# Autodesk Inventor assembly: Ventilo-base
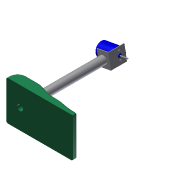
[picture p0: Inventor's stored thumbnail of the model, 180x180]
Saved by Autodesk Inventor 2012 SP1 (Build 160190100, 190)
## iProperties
Created: 2012-06
Part Number: Ventilo-base
Document SubType Name: Assembly
Designer: Bruno
Author: Bruno
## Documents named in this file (8)
- D:\Cours\1-Cours-2012-13\My Box Files\1-ITEC\9-Cinématique-V=W.R-Ventilo\ventilo-2\Ventilo-base.iam
- D:\Cours\1-Cours-2012-13\My Box Files\1-ITEC\9-Cinématique-V=W.R-Ventilo\ventilo-2\Axe.ipt
- D:\Cours\1-Cours-2012-13\My Box Files\1-ITEC\9-Cinématique-V=W.R-Ventilo\ventilo-2\Axe-moteur.ipt
- D:\Cours\1-Cours-2012-13\My Box Files\1-ITEC\9-Cinématique-V=W.R-Ventilo\ventilo-2\corps-moteur.ipt
- D:\Cours\1-Cours-2012-13\My Box Files\1-ITEC\9-Cinématique-V=W.R-Ventilo\ventilo-2\equerre.ipt
- C:\Users\Bruno\Documents\Inventor\Content Center Files\R2012\fr-FR\ANSI B18.6.7M(02)\ANSI B18.6.7M - M4x0,7 x 10(6).ipt
- C:\Users\Bruno\Documents\Inventor\Content Center Files\R2012\fr-FR\JIS B 1111  H (2)\JIS B 1111 - A M2 x 8 - H(1).ipt
- D:\Cours\1-Cours-2012-13\My Box Files\1-ITEC\9-Cinématique-V=W.R-Ventilo\ventilo-2\embase-2.ipt
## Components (8 placed, 7 different names)
1. embase-2:1 — Logement:23
2. Axe:1 — Logement:12, Logement:23
3. Axe-moteur:1 — Placage:4, Affleurement:1
4. corps-moteur:1 — Placage:4, Affleurement:1, Affleurement:2, Placage:16
5. equerre:1 — Affleurement:2, Logement:12, Logement:13, Placage:16, Logement:14, Logement:15
6. Vis à tête carrée - Type III - Métrique M4x0,7 x 10:1 — Logement:13
7. JIS B 1111 H - Métrique A M2 x 8 - H:1 — Logement:14
8. JIS B 1111 H - Métrique A M2 x 8 - H:2 — Logement:15
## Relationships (9: Insert 5, Mate 2, Flush 2)
- Placage:4 [Mate]: Axe-moteur:1 ↔ corps-moteur:1
- Affleurement:1 [Flush]: Axe-moteur:1 ↔ corps-moteur:1
- Affleurement:2 [Flush]: corps-moteur:1 ↔ equerre:1
- Logement:12 [Insert]: Axe:1 ↔ equerre:1
- Logement:13 [Insert]: equerre:1 ↔ Vis à tête carrée - Type III - Métrique M4x0,7 x 10:1
- Placage:16 [Mate]: corps-moteur:1 ↔ equerre:1
- Logement:14 [Insert]: equerre:1 ↔ JIS B 1111 H - Métrique A M2 x 8 - H:1
- Logement:15 [Insert]: equerre:1 ↔ JIS B 1111 H - Métrique A M2 x 8 - H:2
- Logement:23 [Insert]: embase-2:1 ↔ Axe:1
